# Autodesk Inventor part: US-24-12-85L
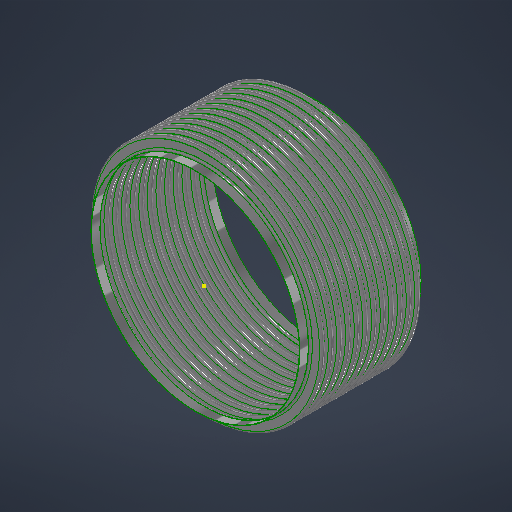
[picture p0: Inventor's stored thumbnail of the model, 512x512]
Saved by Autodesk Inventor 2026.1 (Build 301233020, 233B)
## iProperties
Category: 18 GA (0.048 THICK)
RuleStatus: InUse
Created: 2026-07
Part Number: US-24-12-85L
Project: =STOCK BELLOWS: <Stock Number><SFILL>
Material: ASTM A240-304
Description: =STOCK BELLOWS: <Stock Number>, <SID_> I.D., <SOD_> O.D., <SPLY_> PLY, <Category>, <SNET_CONS> CONS.<PITCH_><STANGENT_> TANGENT<SFILL>
Document SubType Name: Sheet Metal
Designer: LC
Stock Number: U.S-24-12-85L
Surface Area: 659.127 cm^2
Volume: 56.61 cm^3
Sheet Metal Rule: Default
Appearance: STAINLESS STEEL
NET_TUBE: 3.428
COUNTER: 1.500
PBAR: 1.214
PSET: 5.356
PLY: 2
CONS: 2
THK: 0.036
ID: 4.500
OD: 5.500
CONS_: 2
TANGENT: 0.500
PITCH: 0.375
BELLOWS_UPSET: 0.000
NET_CONS: 2
S_CONS: 0
Description_Units: 0
ID_M: 114.30 mm
OD_M: 139.70 mm
THK_M: 0.91 mm
ID_U: 4.500 in
OD_U: 5.500 in
THK_U: 0.036 in
TANGENT2: 0.500
d79: 1.000
d82: 1.000
d83: 26.000
d84: 24.000
d80: 2.571
d81: 10
SID: 2.375
SCONS_: 12
SPITCH: 0.250
SBELLOWS_UPSET: 0.000
SNET_CONS: 12
SS_CONS: 0
SCONS: 8
d174: 8
d177: 0.018
d178: 2.375
d179: 3.000
d180: 0.375
d181: 1.000
d182: 0.000
d190: 8
d191: 1
d192: 1
d193: 8
d194: 0
PART_NUMBER: U.S-24-12-85L
PRESSURE: 85
SIZE: 24.00
STANGENT_: 1.000
d214: 8
d217: 0.030
d218: 6.625
d219: 8.125
d220: 0.500
d221: 1.000
d222: 0.000
d230: 8
d231: 1
d232: 1
d233: 8
d234: 0
STANGENT: 4.000
SPLY_: 1
STHK_: 0.048
SID_: 24.000
SOD_: 26.750
SPITCH_: 1.000
STANGENT__: 1.000
SBELLOWS_UPSET_: 0.000
SDIFF_TAN: 1.000
TAN_TO_TAN: 0.750 in
d252: 2
d275: 2
d287: 0.050
d289: 0.500
d290: 0.000
d263: 2
d265: 1
d268: 2
d269: 0
d286: 2
d288: 1
d291: 2
d292: 0
SOD_NECK: 24 1/8
CFILL: .
SFILL: .
PITCH_: =, <SPITCH_> PITCH,
SREROLL: 0.750
MATTABLE: 20 GA (0.036 THICK)
MESH: ,
CSECT: 2
Author: LC
Keywords: 20 GA (0.036 THICK)
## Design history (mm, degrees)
sketch "Sketch2"
  geometry: L1 (0, -183.595)-(0, 600.956) reference; L2 (58.979, 0)-(57.15, 0); L3 (60.446, -1.467)-(66.554, -1.467); L4 (60.446, -3.296)-(66.554, -3.296); L5 (66.554, -8.058)-(60.446, -8.058); L6 (66.554, -6.229)-(60.446, -6.229); L7 (58.979, -9.525)-(57.15, -9.525); L8 (60.446, 0)-(60.446, -9.525); L9 (66.554, -4.762)-(69.85, -4.763); L10 (57.15, 0)-(57.15, -9.525); L11 (20.376, 102.841)-(20.376, 101.926); L12 (58.262, 488.877)-(58.262, 349.177); L13 (58.262, 479.352)-(58.262, 339.652); L14 (93.133, -58.817)-(93.133, -71.517); L15 (118.746, -66.401)-(118.746, -66.401); L16 (66.554, -6.229)-(66.554, -8.058); L17 (60.446, -6.229)-(60.446, -8.058); L18 (60.446, -7.144)-(66.554, -7.144); L19 (69.85, 0)-(69.85, -9.525); L20 (-66.554, -6.229)-(-66.554, -8.058); L21 (-66.554, -1.467)-(-60.446, -1.467); L22 (-66.554, -3.296)-(-60.446, -3.296); L23 (-60.446, -6.229)-(-66.554, -6.229); L24 (-66.554, -7.144)-(-60.446, -7.144); L25 (-60.446, -8.058)-(-66.554, -8.058); L26 (-60.446, -6.229)-(-60.446, -8.058); L27 (-57.15, -2.522)-(-57.15, -12.047); L28 (-60.446, -4.763)-(-57.15, -4.763); L29 (-66.554, 3.828)-(-66.554, -9.525); L30 (-68.021, 0)-(-69.85, 0); L31 (-69.85, 0)-(-69.85, -9.525); L32 (-68.021, -9.525)-(-69.85, -9.525); A1 r 1.467 centre (60.446, 0) between (58.979, 0) and (60.446, -1.467); A2 r 3.296 centre (60.446, 0) between (57.15, 0) and (60.446, -3.296); A3 r 3.296 centre (66.554, -4.762) between (66.554, -8.058) and (66.554, -1.467); A4 r 1.467 centre (66.554, -4.762) between (66.554, -6.229) and (66.554, -3.296); A5 r 1.467 centre (60.446, -9.525) between (60.446, -8.058) and (58.979, -9.525); A6 r 3.296 centre (60.446, -9.525) between (60.446, -6.229) and (57.15, -9.525); A7 r 2.381 centre (66.554, -4.762) between (66.554, -7.144) and (68.936, -4.762); A8 r 2.381 centre (60.446, -9.525) between (60.446, -7.144) and (58.064, -9.525); A9 r 1.467 centre (-66.554, -9.525) between (-66.554, -8.058) and (-68.021, -9.525); A10 r 1.467 centre (-60.446, -4.763) between (-60.446, -6.229) and (-60.446, -3.296); A11 r 2.381 centre (-60.446, -4.763) between (-60.446, -7.144) and (-58.064, -4.763); A12 r 3.296 centre (-60.446, -4.763) between (-60.446, -8.058) and (-60.446, -1.467); A13 r 2.381 centre (-66.554, -9.525) between (-66.554, -7.144) and (-68.936, -9.525); A14 r 3.296 centre (-66.554, -9.525) between (-66.554, -6.229) and (-69.85, -9.525); A15 r 1.467 centre (-66.554, 0) between (-68.021, 0) and (-66.554, -1.467); A16 r 3.296 centre (-66.554, 0) between (-69.85, 0) and (-66.554, -3.296); 10 further points
  constraints: 62 end point, 38 point on circle, 20 tangent, 16 centre point, 12 parallel, 9 midpoint, 7 vertical, 6 coincident, 6 concentric, 6 point on line, 4 equal radius, 4 perpendicular, 3 horizontal, 1 collinear, 1 horizontal alignment, 10 other
  dimensions: "THK" = 0.9144 distance of L11.start L11.end; "ID" = 114.3 distance of L11.end point (20.376, -12.374); "OD" = 139.7 distance of L12.start L12.end; "PITCH" = 9.525 distance of L12.start L13.start; "TANGENT" = 12.7 distance of L14.start L14.end; "BELLOWS_UPSET" = 0 distance of L15.start L15.end; "d43" = 114.3 diameter of L10 L1 (= ID); "d44" = 139.7 diameter of L9.end L1 (= OD); "d45" = 1.8288 distance between parallel lines of L5 L6 (computed from THK, PLY); "d46" = 3.29565 radius of A3 (computed from PITCH, THK, PLY); "UPSET_PITCH" = 9.525 distance of L2.end L7.end (derived); "SIDEWALL_ANGLE" = 0 deg angle of L3 L9 (derived); "CON_GAP" = 2.9337 distance of point (60.446, -6.229) point (60.446, -3.296) (derived); "TAN1" = 3.74046 dimension on A8 (derived); "TAN2" = 3.74046 dimension on A7 (derived); "LEG1" = 6.1087 distance of L18.start L18.end (derived); "d278" = 1.8288 distance between parallel lines of L25 L23 (derived); "d279" = 3.29565 radius of A12 (derived); "d280" = 9.525 distance of L30.end L31.end (derived); "d281" = 360 deg dimension on L21 L28 (derived); "d282" = 2.9337 distance of point (-66.554, -6.229) point (-66.554, -3.296) (derived); "d283" = 3.74046 dimension on A13 (derived); "d284" = 3.74046 dimension on A11 (derived); "d285" = 6.1087 distance of L24.start L24.end (derived); "d293" = 114.3 diameter of L27 L1 (derived); "d294" = 139.7 diameter of L31 L1 (derived)
  node "Sketch Rectangular Pattern1" dims "d31" = 25.4, "ID" = 114.3
  node "Sketch Rectangular Pattern2" dims "d39" = 25.4, "PITCH" = 9.525
revolve "CONS" stored, may be unused: angle "d48" = 90 deg
node "BELLOW MIDPLANE"
pattern_linear "Rectangular Pattern2" dims "d52" = 9.525 (= UPSET_PITCH)
sketch "Sketch5"
  geometry: C1 r 58.979 at (0, 0) reference; C2 r 57.15 at (0, 0) reference
extrude "TANGENT" new body sketch "Sketch5" distance "d53" = 12.7 (= TANGENT); taper "d54" = 0 deg
revolve "SAMETAN" stored, may be unused: angle "d65" = 90 deg
revolve "DIFFTAN" stored, may be unused: angle "d70" = 90 deg
sketch "Sketch9"
  geometry: L1 (58.391, 0)-(-58.391, 0) reference; L2 (0, -17.78)-(0, 17.78) reference; L3 (41.708, 0)-(-41.708, 0); L4 (41.708, -11.906)-(41.708, 11.906); L5 (29.008, -11.906)-(29.008, 11.906); L6 (15.418, 11.906)-(15.418, -11.906); L7 (-29.008, -11.906)-(-29.008, 11.906); L8 (-41.708, -11.906)-(-41.708, 11.906); L9 (40.914, -11.906)-(40.914, 11.906); L10 (41.708, -11.906)-(40.914, -11.906); L11 (41.708, 11.906)-(40.914, 11.906); L12 (15.815, 11.906)-(15.022, 11.906); L13 (15.022, 11.906)-(15.022, -11.906); L14 (15.022, -11.906)-(15.815, -11.906); L15 (15.815, -11.906)-(15.815, 11.906); L16 (-15.815, 11.906)-(-15.815, -11.906); L17 (-15.418, 11.906)-(-15.418, -11.906); L18 (-15.815, -11.906)-(-15.022, -11.906); L19 (-15.022, -11.906)-(-15.022, 11.906); L20 (-15.022, 11.906)-(-15.815, 11.906); L21 (-41.708, -11.906)-(-40.914, -11.906); L22 (-40.914, -11.906)-(-40.914, 11.906); L23 (-40.914, 11.906)-(-41.708, 11.906); L24 (-41.708, 11.906)-(-41.708, -11.906); L25 (41.708, -0.397)-(-41.708, -0.397); L26 (-41.708, -0.397)-(-41.708, 0.397); L27 (-41.708, 0.397)-(41.708, 0.397); L28 (41.708, 0.397)-(41.708, -0.397); L29 (-41.708, 11.906)-(41.708, 11.906); L30 (41.708, 11.906)-(41.708, 12.7); L31 (41.708, 12.7)-(-41.708, 12.7); L32 (-41.708, 12.7)-(-41.708, 11.906); L33 (41.708, -11.906)-(-41.708, -11.906); L34 (-41.708, -11.906)-(-41.708, -12.7); L35 (-41.708, -12.7)-(41.708, -12.7); L36 (41.708, -12.7)-(41.708, -11.906); 30 further points
  constraints: 68 end point, 13 midpoint, 13 parallel, 8 horizontal, 7 perpendicular, 6 equal length, 3 point on line, 2 vertical, 14 other
  dimensions: "d115" = 23.8125 distance of L4.start L4.end (derived); "d116" = 12.7 distance between parallel lines of L4 L5 (derived); "d117" = 13.58962 distance between parallel lines of L5 L6 (derived); "d125" = 44.42645 distance between parallel lines of L7 L6 (derived); "d127" = 12.7 distance between parallel lines of L8 L7 (derived); "d128" = 26.28962 distance between parallel lines of L6 L4 (derived); "d130" = 83.41607 distance between parallel lines of L8 L4 (derived); "RULER_THK" = 0.79375 distance between parallel lines of L4 L9; "d135" = 0.79375 distance of L13.end L14.end (derived); "d138" = 30.83684 distance of L13.end L16.end (derived); "d143" = 0.79375 distance of L22.end L8.end (derived); "d144" = 0.79375 distance between parallel lines of L27 L25 (derived)
extrude "RULER" join sketch "Sketch9" distance "d149" = 0.79375 (derived); taper "d150" = 0 deg
extrude "BARS" join sketch "Sketch9" distance "d151" = 0.79375 (derived); taper "d152" = 0 deg
pattern_linear "Rectangular Pattern4" dims "d155" = 30.83684 (derived)
sketch "Sketch13"
  geometry: L1 (93.149, -52.467)-(93.149, -77.867); L2 (306.019, 0)-(304.8, 0); L3 (306.019, -25.4)-(304.8, -25.4); L4 (332.765, -19.66)-(311.76, -19.66); L5 (332.765, -18.44)-(311.76, -18.44); L6 (332.765, -12.7)-(339.725, -12.7); L7 (311.76, -5.74)-(332.765, -5.74); L8 (311.76, 0)-(311.76, -25.4); L9 (304.8, 0)-(304.8, -25.4); L10 (58.254, -167.289)-(58.254, -846.739); L11 (58.254, -192.689)-(58.254, -872.139); L12 (58.254, -243.489)-(58.254, -922.939); L13 (58.254, -268.889)-(58.254, -948.339); L14 (58.254, -294.289)-(58.254, -973.739); L15 (58.254, -319.689)-(58.254, -999.139); L16 (58.254, -345.089)-(58.254, -1024.539); L17 (58.254, -218.089)-(58.254, -897.539); L18 (20.376, 103.145)-(20.376, 101.926); L19 (311.76, -6.96)-(332.765, -6.96); L20 (0, -1209.436)-(0, 321.909) reference; L21 (-62.865, 0)-(377.19, 0) reference; A1 r 5.74 centre (311.76, 0) between (306.019, 0) and (311.76, -5.74); A2 r 5.74 centre (311.76, -25.4) between (311.76, -19.66) and (306.019, -25.4); A3 r 6.96 centre (311.76, -25.4) between (311.76, -18.44) and (304.8, -25.4); A4 r 5.74 centre (332.765, -12.7) between (332.765, -18.44) and (332.765, -6.96); A5 r 6.96 centre (332.765, -12.7) between (332.765, -19.66) and (332.765, -5.74); A6 r 6.96 centre (311.76, 0) between (304.8, 0) and (311.76, -6.96); 6 further points; 1 other entity
  constraints: 38 end point, 15 point on circle, 9 tangent, 6 centre point, 6 parallel, 5 vertical alignment, 4 point on line, 4 vertical, 3 coincident, 3 concentric, 2 collinear, 2 equal radius, 1 horizontal, 1 perpendicular, 23 other
  dimensions: "SBELLOWS_UPSET_" = 0 distance of point (118.762, -66.401) point (118.762, -66.401); "STOTAL_THK_BELLOW__" = 1.2192 distance between parallel lines of L4 L5 (derived); "d224" = 6.9596 radius of A5 (derived); "d225" = 25.4 distance of L2.end L3.end (derived); "SSIDEWALL_ANGLE_" = 0 deg angle of L7 L6 (derived); "SSCON_GAP_" = 11.4808 distance of point (311.76, -18.44) point (311.76, -6.96) (derived); "d235" = 609.6 diameter of L9 L20 (derived); "d236" = 679.45 diameter of L6.end L20 (derived)
  node "Sketch Rectangular Pattern4" dims "d228" = 25.4
  node "Sketch Rectangular Pattern5" dims "d229" = 25.4
revolve "SBELLOW" stored, may be unused: angle "d197" = 90 deg
pattern_linear "Rectangular Pattern5" dims "d204" = 25.4 (derived)
revolve "STANGENT" stored, may be unused: angle "d240" = 90 deg
revolve "SSAMETAN" stored, may be unused: angle "d241" = 90 deg
revolve "SDIFFTAN" stored, may be unused: angle "d246" = 90 deg
revolve "INVCON" stored, may be unused: angle "d295" = 90 deg
pattern_linear "Rectangular Pattern6" dims "d298" = 9.525 (derived)
revolve "INVTANGENT" stored, may be unused: angle "d302" = 90 deg
revolve "INVSAMETAN" stored, may be unused: angle "d307" = 90 deg
revolve "INVDIFFTAN" stored, may be unused: angle "d312" = 90 deg
sketch "ID BELLOW MOUNT CALC"
  geometry: L1 (44.45, 0)-(38.1, 0); L2 (38.1, 0)-(38.1, 12.7); L3 (38.1, 12.7)-(44.45, 12.7); L4 (44.45, 12.7)-(44.45, 0); L5 (36.513, 12.7)-(34.684, 12.7); L6 (34.684, 12.7)-(34.684, 0); L7 (34.684, 0)-(36.513, 0); L8 (36.513, 0)-(36.513, 12.7); L9 (0, -2.54)-(0, 15.24) reference; L10 (-8.89, 0)-(53.34, 0) reference; 1 further point
  constraints: 16 end point, 5 parallel, 2 collinear, 2 horizontal, 2 perpendicular
  dimensions: "d314" = 12.7 distance of L5.end L6.end (derived); "d315" = 1.8288 distance of L5.start L5.end (derived); "IG" = 1.5875 distance between parallel lines of L2 L8; "PIPE_OD" = 88.9 diameter of L4 L9; "PIPE_WALL" = 6.35 distance of L2.end L3.end; "ID_MT_BELLOW" = 69.3674 diameter of L6 L9 (derived)
revolve "CFILL" stored, may be unused: angle "d320" = 90 deg
pattern_linear "Rectangular Pattern7" dims "d323" = 9.525 (derived)
revolve "SFILL" stored, may be unused: angle "d324" = 90 deg
pattern_linear "Rectangular Pattern8" dims "d327" = 25.4 (derived)
node "STOCK BELLOW MIDPLANE"
sketch "Sketch21"
  geometry: L1 (0, -100.013)-(0, 100.013) reference; L2 (-100.013, 0)-(100.013, 0) reference; L3 (-0.099, 71.437)-(0.099, 71.437); L4 (0.099, 71.437)-(0.099, 55.562); L5 (0.099, 55.562)-(-0.099, 55.562); L6 (-0.099, 55.562)-(-0.099, 71.437); C1 r 55.562 at (0, 0); C2 r 71.437 at (0, 0); 3 further points
  constraints: 8 end point, 2 centre point, 2 coincident, 2 parallel, 2 tangent, 1 horizontal, 1 perpendicular, 1 other
  dimensions: "d329" = 111.125 diameter of C1 (derived); "d330" = 142.875 diameter of C2 (derived); "d331" = 0.19844 distance of L3.start L3.end
extrude "CLAMSHELL" cut sketch "Sketch21" extent not by distance; stored distance "d332" = 0; taper "d333" = 0 deg
pattern_circular "Circular Pattern1" dims angle "d335" = 180 deg (derived)
node "BELLOW"
sketch "Sketch6"
  geometry: L1 (-19.05, 58.979)-(-6.35, 58.979); L2 (-6.35, 58.979)-(-6.35, 57.15); L3 (-6.35, 57.15)-(-19.05, 57.15); L4 (-19.05, 57.15)-(-19.05, 58.979); L5 (2.54, 0)-(-59.69, 0) reference; L6 (-38.1, -108.388)-(-38.1, 156.601) reference; 1 further point
  constraints: 8 end point, 2 parallel, 1 horizontal, 1 perpendicular
  dimensions: "d61" = 12.7 distance of L2.end L3.end (derived); "d62" = 1.8288 distance of L1.end L2.end (derived); "d63" = 114.3 diameter of L3 L5 (derived); "d64" = 19.05 distance between parallel lines of L4 L6 (derived)
sketch "Sketch12"
  geometry: 1 further point
sketch "Sketch14"
  geometry: L1 (-25.4, 306.019)-(0, 306.019); L2 (0, 306.019)-(0, 304.8); L3 (0, 304.8)-(-25.4, 304.8); L4 (-25.4, 304.8)-(-25.4, 306.019); L5 (5.08, 0)-(-30.48, 0) reference; L6 (0, -56.124)-(0, 336.743) reference; 1 further point
  constraints: 8 end point, 2 parallel, 1 collinear, 1 horizontal, 1 perpendicular
  dimensions: "d237" = 1.2192 distance of L3.end L1.start (derived); "d238" = 609.6 diameter of L3 L5 (derived); "d239" = 25.4 distance of L1.start L1.end (derived); "SOD_NECK" = 612.0384 diameter of L1 L5 (derived)
sketch "Sketch15"
  geometry: L1 (-56.124, 0)-(336.743, 0) reference; L2 (304.8, -304.8)-(306.019, -304.8); L3 (306.019, -304.8)-(306.019, -330.2); L4 (306.019, -330.2)-(304.8, -330.2); L5 (304.8, -330.2)-(304.8, -304.8); L6 (0, -398.78)-(0, 81.28) reference; 1 further point
  constraints: 8 end point, 2 parallel, 1 horizontal, 1 perpendicular
  dimensions: "d205" = 25.4 distance of L4.end L2.start (derived); "d206" = 1.2192 distance of L3.end L4.end (derived); "d207" = 609.6 diameter of L5 L6 (derived); "d208" = 304.8 distance between parallel lines of L1 L2 (derived)
node "TANGENT_"
node "SAME_TAN"
sketch "Sketch8"
  geometry: L1 (58.979, -19.05)-(57.15, -19.05); L2 (57.15, -19.05)-(57.15, -31.75); L3 (57.15, -31.75)-(58.979, -31.75); L4 (58.979, -31.75)-(58.979, -19.05); L5 (0, -40.64)-(0, 21.59) reference; L6 (-108.388, 0)-(156.601, 0) reference; 1 further point
  constraints: 8 end point, 2 parallel, 1 horizontal, 1 perpendicular
  dimensions: "d66" = 114.3 diameter of L2 L5 (derived); "TOTAL_THK_BELLOW" = 1.8288 distance of L2.end L3.end (derived); "d68" = 19.05 distance between parallel lines of L1 L6 (derived); "d69" = 12.7 distance of L1.end L2.end (derived)
node "DIFF_TAN"
node "Sketch Rectangular Pattern3" dims "d138" = 30.83684 (derived), "d141" = 25.4
node "SBELLOW_"
node "STANGENT_"
node "SSAME_TAN"
sketch "Sketch16"
  geometry: L1 (306.019, -304.8)-(304.8, -304.8); L2 (304.8, -304.8)-(304.8, -330.2); L3 (304.8, -330.2)-(306.019, -330.2); L4 (306.019, -330.2)-(306.019, -304.8); L5 (0, -398.78)-(0, 81.28) reference; L6 (-56.124, 0)-(336.743, 0) reference; 1 further point
  constraints: 8 end point, 2 parallel, 1 horizontal, 1 perpendicular
  dimensions: "SDIFF_TAN" = 25.4 distance of L3.end L1.start; "d243" = 1.2192 distance of L2.end L3.end (derived); "d244" = 304.8 distance between parallel lines of L1 L6 (derived); "d245" = 609.6 diameter of L2 L5 (derived)
node "SDIFF_TAN"
body "Solid15"
sketch "Sketch17"
  geometry: L1 (69.85, 12.7)-(68.021, 12.7); L2 (68.021, 12.7)-(68.021, 0); L3 (68.021, 0)-(69.85, 0); L4 (69.85, 0)-(69.85, 12.7); L5 (0, -2.54)-(0, 15.24) reference; L6 (-13.97, 0)-(83.82, 0) reference; 2 further points
  constraints: 8 end point, 2 parallel, 1 horizontal, 1 midpoint, 1 perpendicular, 1 point on line
  dimensions: "INVTANGENT" = 12.7 distance of L3.end L1.start (derived); "d300" = 1.8288 distance of L1.start L1.end (derived); "d301" = 139.7 diameter of L4 L5 (derived)
body "Solid16"
sketch "Sketch18"
  geometry: L1 (69.85, -19.05)-(68.021, -19.05); L2 (68.021, -19.05)-(68.021, -31.75); L3 (68.021, -31.75)-(69.85, -31.75); L4 (69.85, -31.75)-(69.85, -19.05); L5 (-13.97, 0)-(83.82, 0) reference; L6 (0, -40.64)-(0, 21.59) reference; 1 further point
  constraints: 8 end point, 2 parallel, 1 horizontal, 1 perpendicular
  dimensions: "d303" = 19.05 distance between parallel lines of L1 L5 (derived); "d304" = 12.7 distance of L3.end L1.start (derived); "d305" = 1.8288 distance of L2.end L3.end (derived); "d306" = 139.7 diameter of L4 L6 (derived)
body "Solid17"
sketch "Sketch19"
  geometry: L1 (69.85, -19.05)-(68.021, -19.05); L2 (68.021, -19.05)-(68.021, -31.75); L3 (68.021, -31.75)-(69.85, -31.75); L4 (69.85, -31.75)-(69.85, -19.05); L5 (0, -40.64)-(0, 21.59) reference; L6 (-13.97, 0)-(83.82, 0) reference; 1 further point
  constraints: 8 end point, 2 parallel, 1 horizontal, 1 perpendicular
  dimensions: "d308" = 12.7 distance of L1.end L2.end (derived); "d309" = 139.7 diameter of L4 L5 (derived); "d310" = 1.8288 distance of L2.end L3.end (derived); "d311" = 19.05 distance between parallel lines of L1 L6 (derived)
body "Solid18"
body "Solid19"
body "Solid20"
other parameters: "BMPL" = -152.4, "PSET" = 136.0424 (computed from OD, THK, PLY) [user parameter], "PBAR" = 30.83684 (= 0.570796 x PITCH + OD - ID) [user parameter; used in 1 equation term], "COUNTER" = 15 [user parameter], "NET_TUBE" = 87.07367 (computed from CONS_, PBAR, TANGENT) [user parameter], "S_CONS" = 0 [user parameter; used in 1 equation term], "ID_M" = 114.3 (= ID) [user parameter], "OD_M" = 139.7 (= OD) [user parameter], "THK_M" = 0.9144 (= THK) [user parameter], "ID_U" = 114.3 (= ID) [user parameter], "OD_U" = 139.7 (= OD) [user parameter], "THK_U" = 0.9144 (= THK) [user parameter], "D_UNITS" = 0 [user parameter], "TANGENT2" = 12.7 [user parameter], "TAN_TO_TAN" = 19.05 [user parameter], "OD_NECK" = 117.9576 [user parameter], "d79" = 25.4, "d80" = 65.29823 [user parameter], "d82" = 25.4, "d83" = 660.4, "d84" = 609.6, "sa_0" = 4, "FRAME_THK" = 0.79375 [user parameter], "CON_FLAT" = 13.58962 [user parameter], "SID" = 60.325 [user parameter], "SPITCH" = 6.35 [user parameter], "STANGENT_" = 25.4 [user parameter], "SBELLOWS_UPSET" = 0 [user parameter], "SS_CONS" = 0 [user parameter], "STAN_TO_TAN_" = 304.8 [user parameter], "d100" = 1.2192 [user parameter], "d191" = 25.4 [user parameter], "d194" = 0 [user parameter], "STANGENT" = 101.6 [user parameter], "d234" = 0 [user parameter], "SUPSET_PITCH_" = 25.4 [user parameter], "d269" = 0 [user parameter], "d287" = 1.27, "d289" = 12.7, "d290" = 0, "d292" = 0 [user parameter], "Thickness" = 3.048 (derived), "KFactor" = 4.4, "BendRadius" = 3.048 (derived), "BendReliefWidth" = 3.048 (derived), "BendReliefDepth" = 1.524 (derived), "CornerReliefSize" = 12.192 (derived), "SeamGap" = 0.00508, "MinimumRemnant" = 6.096 (derived), "TransitionRadius" = 3.048 (derived), "JacobiRadiusSize" = 3.048 (derived), "GapSize" = 3.048 (derived), "SREROLL" = 19.05 [user parameter], "CUR_STK_PITCH" = 25.4 [user parameter], "d328" = -152.4 (derived), "CSECTDEG" = 180 deg [user parameter]
